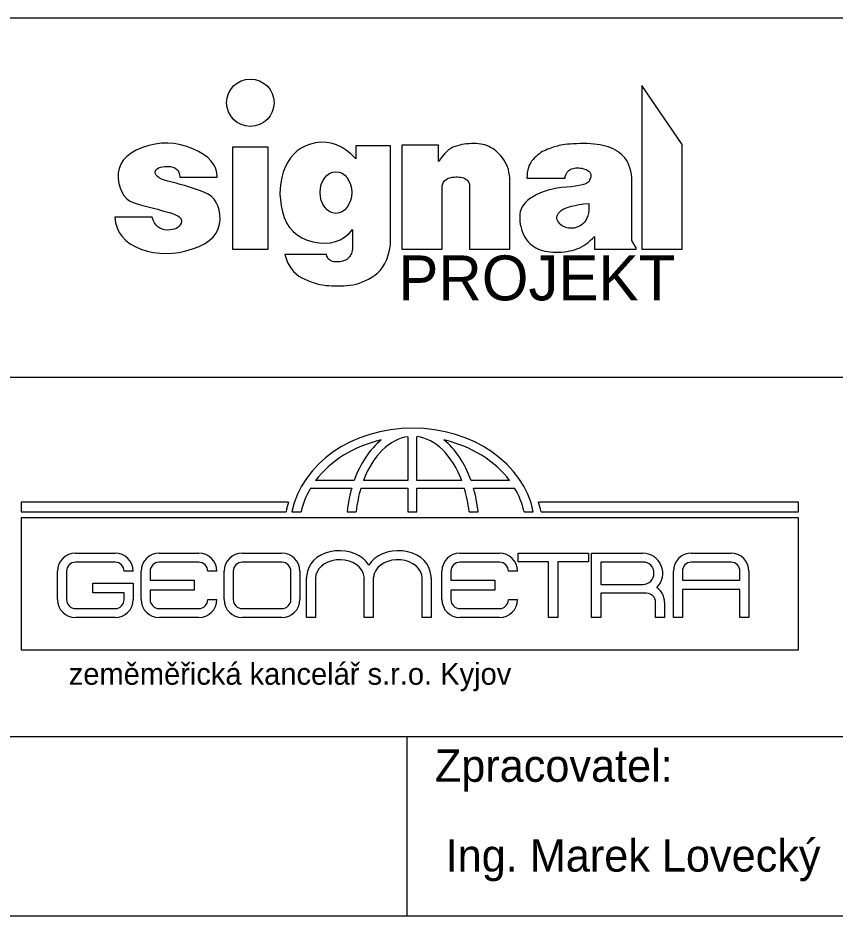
# Model space of a CAD drawing. Extents: x -553916 to -552953, y -1067469 to -1066637.
# Drawn here: x -553034.4 to -552988.9, y -1067308.3 to -1067258.3 of the extents above; entities that cross this region are included whole.
import ezdxf

# ---------------------------------------------------------------- set-up
doc = ezdxf.new("R2010")
doc.units = 0
for name, color, linetype in [('ROZPISKA', 7, 'Continuous'), ('Rozpiska_pole_6', 7, 'Continuous'), ('ZZZ - Razítko', 7, 'Continuous')]:
    doc.layers.add(name, color=color, linetype=linetype)

msp = doc.modelspace()

# ---------------------------------------------------------------- linework, layer by layer
at = {"layer": 'ROZPISKA'}
for points in [[(-552997.445, -1067271.147), (-552997.445, -1067265.307), (-552999.685, -1067262.027), (-552999.685, -1067271.147), (-552997.445, -1067271.147)], [(-553026.174, -1067271.382), (-553025.812, -1067271.366), (-553025.445, -1067271.318), (-553025.074, -1067271.239), (-553024.698, -1067271.128), (-553024.344, -1067270.992), (-553024.036, -1067270.836), (-553023.775, -1067270.66), (-553023.561, -1067270.464), (-553023.393, -1067270.248), (-553023.273, -1067270.012), (-553023.199, -1067269.756), (-553023.173, -1067269.481), (-553023.183, -1067269.207), (-553023.222, -1067268.958), (-553023.288, -1067268.734), (-553023.382, -1067268.535), (-553023.503, -1067268.36), (-553023.652, -1067268.21), (-553023.829, -1067268.084), (-553024.034, -1067267.984), (-553024.253, -1067267.898), (-553024.475, -1067267.816), (-553024.699, -1067267.738), (-553024.926, -1067267.666), (-553025.155, -1067267.597), (-553025.386, -1067267.533), (-553025.619, -1067267.473), (-553025.855, -1067267.418), (-553026.077, -1067267.363), (-553026.268, -1067267.304), (-553026.428, -1067267.241), (-553026.559, -1067267.174), (-553026.659, -1067267.102), (-553026.728, -1067267.027), (-553026.767, -1067266.948), (-553026.776, -1067266.865), (-553026.759, -1067266.785), (-553026.723, -1067266.717), (-553026.667, -1067266.659), (-553026.591, -1067266.611), (-553026.495, -1067266.575), (-553026.379, -1067266.55), (-553026.244, -1067266.535), (-553026.088, -1067266.531), (-553025.933, -1067266.542), (-553025.798, -1067266.571), (-553025.683, -1067266.619), (-553025.588, -1067266.684), (-553025.513, -1067266.768), (-553025.459, -1067266.87), (-553025.424, -1067266.991), (-553025.41, -1067267.129), (-553023.331, -1067267.129), (-553023.35, -1067266.888), (-553023.412, -1067266.658), (-553023.517, -1067266.441), (-553023.665, -1067266.237), (-553023.856, -1067266.045), (-553024.09, -1067265.866), (-553024.366, -1067265.7), (-553024.686, -1067265.547), (-553025.028, -1067265.417), (-553025.373, -1067265.323), (-553025.721, -1067265.263), (-553026.071, -1067265.238), (-553026.424, -1067265.248), (-553026.779, -1067265.293), (-553027.138, -1067265.373), (-553027.498, -1067265.487), (-553027.836, -1067265.63), (-553028.126, -1067265.792), (-553028.366, -1067265.976), (-553028.559, -1067266.18), (-553028.702, -1067266.404), (-553028.797, -1067266.649), (-553028.843, -1067266.914), (-553028.841, -1067267.2), (-553028.801, -1067267.482), (-553028.735, -1067267.734), (-553028.643, -1067267.956), (-553028.524, -1067268.149), (-553028.38, -1067268.312), (-553028.209, -1067268.446), (-553028.012, -1067268.55), (-553027.788, -1067268.625), (-553027.553, -1067268.685), (-553027.322, -1067268.745), (-553027.095, -1067268.804), (-553026.871, -1067268.863), (-553026.65, -1067268.921), (-553026.434, -1067268.98), (-553026.221, -1067269.038), (-553026.011, -1067269.096), (-553025.819, -1067269.156), (-553025.657, -1067269.22), (-553025.527, -1067269.289), (-553025.427, -1067269.362), (-553025.359, -1067269.44), (-553025.321, -1067269.523), (-553025.314, -1067269.609), (-553025.338, -1067269.701), (-553025.384, -1067269.789), (-553025.445, -1067269.865), (-553025.521, -1067269.93), (-553025.611, -1067269.983), (-553025.715, -1067270.024), (-553025.833, -1067270.054), (-553025.966, -1067270.073), (-553026.113, -1067270.079), (-553026.262, -1067270.069), (-553026.398, -1067270.036), (-553026.521, -1067269.98), (-553026.632, -1067269.902), (-553026.731, -1067269.8), (-553026.818, -1067269.677), (-553026.892, -1067269.53), (-553026.953, -1067269.362), (-553029.034, -1067269.362), (-553028.99, -1067269.668), (-553028.906, -1067269.951), (-553028.783, -1067270.208), (-553028.621, -1067270.442), (-553028.418, -1067270.652), (-553028.177, -1067270.837), (-553027.895, -1067270.998), (-553027.574, -1067271.134), (-553027.231, -1067271.243), (-553026.883, -1067271.321), (-553026.531, -1067271.367), (-553026.174, -1067271.382)], [(-553020.485, -1067271.147), (-553020.485, -1067265.467), (-553022.485, -1067265.467), (-553022.485, -1067271.147), (-553020.485, -1067271.147)], [(-553016.626, -1067273.189), (-553016.457, -1067273.186), (-553016.287, -1067273.177), (-553016.115, -1067273.164), (-553015.942, -1067273.145), (-553015.768, -1067273.119), (-553015.594, -1067273.08), (-553015.42, -1067273.028), (-553015.246, -1067272.965), (-553015.073, -1067272.89), (-553014.9, -1067272.802), (-553014.728, -1067272.702), (-553014.556, -1067272.59), (-553014.391, -1067272.461), (-553014.243, -1067272.308), (-553014.11, -1067272.132), (-553013.994, -1067271.933), (-553013.893, -1067271.711), (-553013.808, -1067271.466), (-553013.739, -1067271.198), (-553013.685, -1067270.907), (-553013.685, -1067265.387), (-553015.605, -1067265.387), (-553015.605, -1067266.107), (-553015.871, -1067265.853), (-553016.142, -1067265.64), (-553016.416, -1067265.468), (-553016.695, -1067265.337), (-553016.978, -1067265.247), (-553017.266, -1067265.198), (-553017.557, -1067265.19), (-553017.853, -1067265.224), (-553018.14, -1067265.292), (-553018.406, -1067265.389), (-553018.649, -1067265.514), (-553018.871, -1067265.668), (-553019.071, -1067265.85), (-553019.249, -1067266.061), (-553019.406, -1067266.301), (-553019.541, -1067266.568), (-553019.651, -1067266.854), (-553019.736, -1067267.147), (-553019.795, -1067267.447), (-553019.828, -1067267.755), (-553019.835, -1067268.069), (-553019.816, -1067268.391), (-553019.772, -1067268.72), (-553019.701, -1067269.056), (-553019.601, -1067269.379), (-553019.468, -1067269.67), (-553019.303, -1067269.928), (-553019.105, -1067270.154), (-553018.874, -1067270.346), (-553018.611, -1067270.506), (-553018.314, -1067270.634), (-553017.986, -1067270.728), (-553017.649, -1067270.786), (-553017.331, -1067270.804), (-553017.03, -1067270.78), (-553016.747, -1067270.716), (-553016.482, -1067270.612), (-553016.235, -1067270.466), (-553016.005, -1067270.28), (-553015.793, -1067270.053), (-553015.793, -1067271.13), (-553015.812, -1067271.217), (-553015.835, -1067271.299), (-553015.862, -1067271.375), (-553015.895, -1067271.445), (-553015.931, -1067271.51), (-553015.972, -1067271.568), (-553016.018, -1067271.621), (-553016.067, -1067271.669), (-553016.123, -1067271.71), (-553016.186, -1067271.747), (-553016.256, -1067271.778), (-553016.333, -1067271.803), (-553016.417, -1067271.823), (-553016.508, -1067271.838), (-553016.606, -1067271.847), (-553016.711, -1067271.851), (-553016.815, -1067271.846), (-553016.908, -1067271.827), (-553016.991, -1067271.796), (-553017.064, -1067271.751), (-553017.127, -1067271.692), (-553017.18, -1067271.621), (-553017.222, -1067271.536), (-553017.254, -1067271.438), (-553019.562, -1067271.438), (-553019.492, -1067271.665), (-553019.409, -1067271.874), (-553019.312, -1067272.064), (-553019.201, -1067272.236), (-553019.077, -1067272.388), (-553018.938, -1067272.522), (-553018.786, -1067272.637), (-553018.62, -1067272.734), (-553018.448, -1067272.817), (-553018.277, -1067272.891), (-553018.108, -1067272.956), (-553017.94, -1067273.013), (-553017.774, -1067273.062), (-553017.609, -1067273.102), (-553017.446, -1067273.133), (-553017.284, -1067273.155), (-553017.122, -1067273.171), (-553016.958, -1067273.182), (-553016.793, -1067273.188), (-553016.626, -1067273.189)], [(-553007.045, -1067271.147), (-553007.045, -1067267.347), (-553007.048, -1067267.177), (-553007.062, -1067267.014), (-553007.087, -1067266.857), (-553007.123, -1067266.707), (-553007.169, -1067266.564), (-553007.226, -1067266.427), (-553007.294, -1067266.297), (-553007.372, -1067266.173), (-553007.457, -1067266.057), (-553007.544, -1067265.949), (-553007.633, -1067265.849), (-553007.724, -1067265.757), (-553007.817, -1067265.674), (-553007.912, -1067265.598), (-553008.009, -1067265.531), (-553008.108, -1067265.473), (-553008.211, -1067265.421), (-553008.317, -1067265.377), (-553008.428, -1067265.34), (-553008.543, -1067265.309), (-553008.662, -1067265.286), (-553008.786, -1067265.269), (-553008.914, -1067265.259), (-553009.046, -1067265.257), (-553009.18, -1067265.26), (-553009.312, -1067265.268), (-553009.444, -1067265.281), (-553009.574, -1067265.299), (-553009.703, -1067265.322), (-553009.831, -1067265.35), (-553009.957, -1067265.382), (-553010.083, -1067265.42), (-553010.206, -1067265.468), (-553010.328, -1067265.533), (-553010.447, -1067265.614), (-553010.563, -1067265.712), (-553010.677, -1067265.826), (-553010.789, -1067265.957), (-553010.898, -1067266.104), (-553011.005, -1067266.267), (-553011.005, -1067265.347), (-553013.045, -1067265.347), (-553013.045, -1067271.147), (-553010.805, -1067271.147), (-553010.805, -1067267.587), (-553010.771, -1067267.496), (-553010.726, -1067267.415), (-553010.672, -1067267.344), (-553010.608, -1067267.283), (-553010.534, -1067267.232), (-553010.45, -1067267.191), (-553010.356, -1067267.16), (-553010.252, -1067267.139), (-553010.146, -1067267.126), (-553010.045, -1067267.119), (-553009.95, -1067267.118), (-553009.859, -1067267.124), (-553009.774, -1067267.135), (-553009.695, -1067267.153), (-553009.62, -1067267.176), (-553009.551, -1067267.206), (-553009.489, -1067267.241), (-553009.435, -1067267.279), (-553009.389, -1067267.321), (-553009.352, -1067267.367), (-553009.323, -1067267.417), (-553009.302, -1067267.47), (-553009.289, -1067267.527), (-553009.285, -1067267.587), (-553009.285, -1067271.147), (-553007.045, -1067271.147)], [(-553004.482, -1067271.311), (-553004.321, -1067271.308), (-553004.163, -1067271.3), (-553004.01, -1067271.285), (-553003.861, -1067271.265), (-553003.716, -1067271.24), (-553003.576, -1067271.208), (-553003.44, -1067271.171), (-553003.308, -1067271.128), (-553003.18, -1067271.076), (-553003.053, -1067271.015), (-553002.927, -1067270.943), (-553002.804, -1067270.861), (-553002.682, -1067270.768), (-553002.561, -1067270.665), (-553002.442, -1067270.551), (-553002.325, -1067270.427), (-553002.325, -1067271.147), (-553000.005, -1067271.147), (-553000.005, -1067271.067), (-553000.245, -1067270.667), (-553000.245, -1067267.187), (-553000.272, -1067266.983), (-553000.307, -1067266.792), (-553000.353, -1067266.617), (-553000.408, -1067266.456), (-553000.472, -1067266.309), (-553000.546, -1067266.177), (-553000.63, -1067266.059), (-553000.723, -1067265.955), (-553000.824, -1067265.863), (-553000.931, -1067265.777), (-553001.045, -1067265.698), (-553001.165, -1067265.626), (-553001.291, -1067265.561), (-553001.423, -1067265.503), (-553001.562, -1067265.452), (-553001.707, -1067265.408), (-553001.859, -1067265.37), (-553002.018, -1067265.338), (-553002.184, -1067265.311), (-553002.358, -1067265.29), (-553002.538, -1067265.275), (-553002.726, -1067265.266), (-553002.922, -1067265.262), (-553003.124, -1067265.265), (-553003.323, -1067265.271), (-553003.507, -1067265.279), (-553003.676, -1067265.289), (-553003.83, -1067265.302), (-553003.97, -1067265.317), (-553004.095, -1067265.334), (-553004.206, -1067265.354), (-553004.301, -1067265.375), (-553004.39, -1067265.399), (-553004.479, -1067265.425), (-553004.569, -1067265.452), (-553004.66, -1067265.482), (-553004.751, -1067265.513), (-553004.844, -1067265.547), (-553004.936, -1067265.582), (-553005.03, -1067265.62), (-553005.123, -1067265.661), (-553005.215, -1067265.71), (-553005.306, -1067265.765), (-553005.397, -1067265.827), (-553005.486, -1067265.896), (-553005.574, -1067265.972), (-553005.661, -1067266.055), (-553005.747, -1067266.144), (-553005.827, -1067266.242), (-553005.897, -1067266.349), (-553005.955, -1067266.465), (-553006.003, -1067266.591), (-553006.04, -1067266.726), (-553006.066, -1067266.87), (-553006.081, -1067267.024), (-553006.085, -1067267.187), (-553003.965, -1067267.187), (-553003.95, -1067267.091), (-553003.926, -1067267.004), (-553003.893, -1067266.926), (-553003.851, -1067266.857), (-553003.801, -1067266.797), (-553003.743, -1067266.747), (-553003.675, -1067266.705), (-553003.599, -1067266.673), (-553003.519, -1067266.649), (-553003.438, -1067266.631), (-553003.356, -1067266.619), (-553003.274, -1067266.615), (-553003.192, -1067266.616), (-553003.108, -1067266.625), (-553003.025, -1067266.639), (-553002.94, -1067266.661), (-553002.86, -1067266.686), (-553002.789, -1067266.714), (-553002.726, -1067266.744), (-553002.673, -1067266.776), (-553002.627, -1067266.81), (-553002.591, -1067266.846), (-553002.563, -1067266.885), (-553002.545, -1067266.925), (-553002.533, -1067266.968), (-553002.528, -1067267.014), (-553002.529, -1067267.063), (-553002.537, -1067267.114), (-553002.55, -1067267.168), (-553002.57, -1067267.225), (-553002.597, -1067267.285), (-553002.629, -1067267.348), (-553002.68, -1067267.409), (-553002.761, -1067267.465), (-553002.872, -1067267.515), (-553003.014, -1067267.561), (-553003.186, -1067267.601), (-553003.388, -1067267.636), (-553003.621, -1067267.665), (-553003.884, -1067267.689), (-553004.156, -1067267.716), (-553004.415, -1067267.753), (-553004.662, -1067267.801), (-553004.897, -1067267.86), (-553005.12, -1067267.929), (-553005.331, -1067268.008), (-553005.529, -1067268.098), (-553005.715, -1067268.199), (-553005.884, -1067268.307), (-553006.032, -1067268.42), (-553006.16, -1067268.537), (-553006.266, -1067268.659), (-553006.352, -1067268.785), (-553006.417, -1067268.915), (-553006.461, -1067269.051), (-553006.484, -1067269.19), (-553006.492, -1067269.332), (-553006.491, -1067269.472), (-553006.481, -1067269.611), (-553006.462, -1067269.749), (-553006.434, -1067269.885), (-553006.397, -1067270.021), (-553006.351, -1067270.155), (-553006.296, -1067270.288), (-553006.233, -1067270.417), (-553006.163, -1067270.536), (-553006.086, -1067270.646), (-553006.002, -1067270.748), (-553005.911, -1067270.84), (-553005.814, -1067270.924), (-553005.709, -1067270.999), (-553005.598, -1067271.065), (-553005.48, -1067271.123), (-553005.356, -1067271.173), (-553005.226, -1067271.215), (-553005.089, -1067271.25), (-553004.947, -1067271.277), (-553004.798, -1067271.296), (-553004.643, -1067271.307), (-553004.482, -1067271.311)], [(-553003.767, -1067269.967), (-553003.87, -1067269.946), (-553003.964, -1067269.918), (-553004.051, -1067269.882), (-553004.13, -1067269.839), (-553004.201, -1067269.787), (-553004.264, -1067269.728), (-553004.319, -1067269.661), (-553004.365, -1067269.587), (-553004.4, -1067269.509), (-553004.418, -1067269.432), (-553004.419, -1067269.356), (-553004.403, -1067269.281), (-553004.371, -1067269.207), (-553004.322, -1067269.134), (-553004.256, -1067269.061), (-553004.173, -1067268.99), (-553004.07, -1067268.922), (-553003.941, -1067268.859), (-553003.787, -1067268.801), (-553003.608, -1067268.748), (-553003.404, -1067268.701), (-553003.175, -1067268.659), (-553002.92, -1067268.623), (-553002.64, -1067268.592), (-553002.636, -1067268.79), (-553002.645, -1067268.972), (-553002.667, -1067269.138), (-553002.701, -1067269.288), (-553002.749, -1067269.421), (-553002.809, -1067269.539), (-553002.882, -1067269.64), (-553002.969, -1067269.725), (-553003.062, -1067269.797), (-553003.158, -1067269.856), (-553003.255, -1067269.904), (-553003.354, -1067269.94), (-553003.454, -1067269.964), (-553003.557, -1067269.977), (-553003.661, -1067269.978), (-553003.767, -1067269.967)]]:
    msp.add_lwpolyline(points, dxfattribs=at)
msp.add_circle((-553021.485, -1067262.987), 1.32, dxfattribs=at)
msp.add_ellipse((-553016.725, -1067267.987), major_axis=(0, 1.16), ratio=0.758621, dxfattribs=at)
at = {"layer": 'Rozpiska_pole_6'}
for p, q in [((-553143.11, -1067278.268), (-552973.11, -1067278.268)), ((-553143.11, -1067298.268), (-552973.11, -1067298.268)), ((-553012.76, -1067308.268), (-553012.76, -1067298.268))]:
    msp.add_line(p, q, dxfattribs=at)
msp.add_lwpolyline([(-553143.11, -1067258.268), (-552973.11, -1067258.268), (-552973.11, -1067308.268), (-553143.11, -1067308.268)], close=True, dxfattribs=at)
at = {"layer": 'ZZZ - Razítko'}
for p, q in [((-553012.715, -1067281.581), (-553012.715, -1067284.027)), ((-553012.208, -1067284.027), (-553012.208, -1067281.579)), ((-553018.128, -1067284.438), (-553015.841, -1067284.438)), ((-553015.708, -1067284.027), (-553017.853, -1067284.027)), ((-553015.331, -1067284.438), (-553012.715, -1067284.438)), ((-553012.715, -1067284.027), (-553015.191, -1067284.027)), ((-553012.715, -1067284.438), (-553012.715, -1067285.758)), ((-553009.713, -1067284.027), (-553012.208, -1067284.027)), ((-553012.208, -1067285.758), (-553012.208, -1067284.438)), ((-553012.208, -1067284.438), (-553009.574, -1067284.438)), ((-553007.051, -1067284.027), (-553009.196, -1067284.027)), ((-553009.064, -1067284.438), (-553006.776, -1067284.438)), ((-553019.359, -1067285.227), (-553034.239, -1067285.227)), ((-553034.239, -1067285.227), (-553034.239, -1067285.758)), ((-552990.961, -1067285.227), (-553005.439, -1067285.227)), ((-552990.961, -1067285.758), (-552990.961, -1067285.227)), ((-553034.239, -1067285.758), (-553019.497, -1067285.758)), ((-553019.171, -1067285.758), (-553018.654, -1067285.758)), ((-553016.098, -1067285.758), (-553015.598, -1067285.758)), ((-553012.715, -1067285.758), (-553012.208, -1067285.758)), ((-553009.307, -1067285.758), (-553008.806, -1067285.758)), ((-553006.25, -1067285.758), (-553005.733, -1067285.758)), ((-553005.301, -1067285.758), (-552990.961, -1067285.758)), ((-552990.963, -1067286.103), (-553034.246, -1067286.103)), ((-553034.246, -1067286.103), (-553034.246, -1067293.441)), ((-552990.963, -1067293.441), (-552990.963, -1067286.103)), ((-553031.221, -1067288.069), (-553029.01, -1067288.069)), ((-553026.565, -1067288.069), (-553024.354, -1067288.069)), ((-553021.941, -1067288.069), (-553019.73, -1067288.069)), ((-553009.822, -1067288.069), (-553007.612, -1067288.069)), ((-553002.485, -1067288.069), (-552999.64, -1067288.069)), ((-552996.937, -1067288.069), (-552994.726, -1067288.069)), ((-553029.01, -1067288.567), (-553031.221, -1067288.567)), ((-553024.354, -1067288.567), (-553026.565, -1067288.567)), ((-553019.73, -1067288.567), (-553021.941, -1067288.567)), ((-553007.612, -1067288.567), (-553009.822, -1067288.567)), ((-553004.879, -1067291.651), (-553004.879, -1067288.555)), ((-553004.376, -1067288.555), (-553004.376, -1067291.651)), ((-552999.64, -1067288.558), (-553001.981, -1067288.558)), ((-553001.981, -1067288.558), (-553001.981, -1067289.807)), ((-552994.726, -1067288.567), (-552996.937, -1067288.567)), ((-553032.219, -1067290.653), (-553032.219, -1067289.067)), ((-553031.72, -1067289.067), (-553031.72, -1067290.653)), ((-553028.013, -1067289.067), (-553028.511, -1067289.067)), ((-553027.562, -1067290.653), (-553027.562, -1067289.067)), ((-553027.064, -1067289.067), (-553027.064, -1067289.577)), ((-553023.356, -1067289.067), (-553023.855, -1067289.067)), ((-553022.939, -1067290.653), (-553022.939, -1067289.067)), ((-553022.44, -1067289.067), (-553022.44, -1067290.653)), ((-553019.231, -1067290.653), (-553019.231, -1067289.067)), ((-553018.732, -1067289.067), (-553018.732, -1067290.653)), ((-553018.36, -1067291.651), (-553018.36, -1067289.466)), ((-553017.859, -1067289.466), (-553017.859, -1067291.651)), ((-553015.14, -1067291.651), (-553015.14, -1067289.466)), ((-553014.639, -1067289.466), (-553014.639, -1067291.651)), ((-553011.921, -1067291.651), (-553011.921, -1067289.466)), ((-553011.42, -1067289.466), (-553011.42, -1067291.651)), ((-553010.82, -1067290.653), (-553010.82, -1067289.067)), ((-553010.321, -1067289.067), (-553010.321, -1067289.577)), ((-553006.614, -1067289.067), (-553007.112, -1067289.067)), ((-552997.935, -1067291.651), (-552997.935, -1067289.067)), ((-552997.436, -1067289.067), (-552997.436, -1067289.575)), ((-552994.227, -1067289.575), (-552994.227, -1067289.067)), ((-552993.728, -1067289.067), (-552993.728, -1067291.651)), ((-553030.246, -1067290.275), (-553030.246, -1067289.73)), ((-553030.246, -1067289.73), (-553028.013, -1067289.73)), ((-553028.013, -1067289.73), (-553028.013, -1067290.653)), ((-553027.064, -1067289.577), (-553024.621, -1067289.577)), ((-553024.621, -1067289.577), (-553024.621, -1067290.122)), ((-553010.321, -1067289.577), (-553007.878, -1067289.577)), ((-553007.878, -1067289.577), (-553007.878, -1067290.122)), ((-553001.981, -1067289.807), (-552999.64, -1067289.807)), ((-552997.436, -1067289.575), (-552994.227, -1067289.575)), ((-553028.511, -1067290.275), (-553030.246, -1067290.275)), ((-553028.511, -1067290.653), (-553028.511, -1067290.275)), ((-553024.621, -1067290.122), (-553027.064, -1067290.122)), ((-553027.064, -1067290.122), (-553027.064, -1067290.653)), ((-553007.878, -1067290.122), (-553010.321, -1067290.122)), ((-553010.321, -1067290.122), (-553010.321, -1067290.653)), ((-552999.64, -1067290.296), (-553001.981, -1067290.296)), ((-552999.426, -1067290.3), (-552999.64, -1067290.296)), ((-552994.227, -1067290.079), (-552997.436, -1067290.079)), ((-552997.436, -1067290.079), (-552997.436, -1067291.651)), ((-552994.227, -1067291.651), (-552994.227, -1067290.079)), ((-553023.855, -1067290.653), (-553023.356, -1067290.653)), ((-553007.112, -1067290.653), (-553006.614, -1067290.653)), ((-552998.927, -1067291.651), (-552998.927, -1067290.799)), ((-552998.429, -1067290.799), (-552998.429, -1067291.651)), ((-553031.221, -1067291.152), (-553029.01, -1067291.152)), ((-553026.565, -1067291.152), (-553024.354, -1067291.152)), ((-553021.941, -1067291.152), (-553019.73, -1067291.152)), ((-553009.822, -1067291.152), (-553007.612, -1067291.152)), ((-553029.01, -1067291.651), (-553031.221, -1067291.651)), ((-553024.354, -1067291.651), (-553026.565, -1067291.651)), ((-553019.73, -1067291.651), (-553021.941, -1067291.651)), ((-553017.859, -1067291.651), (-553018.36, -1067291.651)), ((-553014.639, -1067291.651), (-553015.14, -1067291.651)), ((-553011.42, -1067291.651), (-553011.921, -1067291.651)), ((-553007.612, -1067291.651), (-553009.822, -1067291.651)), ((-553004.376, -1067291.651), (-553004.879, -1067291.651)), ((-552998.429, -1067291.651), (-552998.927, -1067291.651)), ((-552997.436, -1067291.651), (-552997.935, -1067291.651)), ((-552993.728, -1067291.651), (-552994.227, -1067291.651)), ((-553034.246, -1067293.441), (-552990.963, -1067293.441))]:
    msp.add_line(p, q, dxfattribs=at)
for points in [[(-553004.879, -1067288.555), (-553006.577, -1067288.555), (-553006.577, -1067288.069), (-553002.663, -1067288.069)], [(-553002.663, -1067288.069), (-553002.663, -1067288.555), (-553004.376, -1067288.555)], [(-553001.981, -1067290.296), (-553001.981, -1067291.651), (-553002.485, -1067291.651), (-553002.485, -1067288.069)]]:
    msp.add_lwpolyline(points, dxfattribs=at)
for centre, radius, start, end in [((-553031.221, -1067289.067), 0.998, 90, 180), ((-553029.01, -1067289.067), 0.998, 360, 90), ((-553026.565, -1067289.067), 0.998, 90, 180), ((-553024.354, -1067289.067), 0.998, 360, 90), ((-553021.941, -1067289.067), 0.998, 90, 180), ((-553019.73, -1067289.067), 0.998, 360, 90), ((-553009.822, -1067289.067), 0.998, 90, 180), ((-553007.612, -1067289.067), 0.998, 360, 90), ((-552999.64, -1067289.183), 1.114, 314.4573, 90), ((-552996.937, -1067289.067), 0.998, 90, 180), ((-552994.726, -1067289.067), 0.998, 360, 90), ((-553031.221, -1067289.067), 0.499, 90, 180), ((-553029.01, -1067289.067), 0.499, 0, 90), ((-553026.565, -1067289.067), 0.499, 90, 180), ((-553024.354, -1067289.067), 0.499, 0, 90), ((-553021.941, -1067289.067), 0.499, 90, 180), ((-553019.73, -1067289.067), 0.499, 0, 90), ((-553009.822, -1067289.067), 0.499, 90, 180), ((-553007.612, -1067289.067), 0.499, 0, 90), ((-552999.64, -1067289.183), 0.625, 270, 90), ((-552996.937, -1067289.067), 0.499, 90, 180), ((-552994.726, -1067289.067), 0.499, 0, 90), ((-553016.422, -1067289.516), 1.938, 166.9658, 178.5209), ((-553016.094, -1067289.53), 0.957, 3.8649, 22.4157), ((-553013.407, -1067289.588), 1.238, 162.6139, 174.3506), ((-553013.358, -1067289.516), 1.938, 1.4791, 13.0342), ((-552999.426, -1067290.799), 0.998, 360, 55.4473), ((-552999.426, -1067290.799), 0.499, 0, 90), ((-553031.221, -1067290.653), 0.998, 180, 270), ((-553031.221, -1067290.653), 0.499, 180, 270), ((-553029.01, -1067290.653), 0.998, 270, 0), ((-553029.01, -1067290.653), 0.499, 270, 0), ((-553026.565, -1067290.653), 0.998, 180, 270), ((-553026.565, -1067290.653), 0.499, 180, 270), ((-553024.354, -1067290.653), 0.998, 270, 0), ((-553024.354, -1067290.653), 0.499, 270, 0), ((-553021.941, -1067290.653), 0.998, 180, 270), ((-553021.941, -1067290.653), 0.499, 180, 270), ((-553019.73, -1067290.653), 0.998, 270, 0), ((-553019.73, -1067290.653), 0.499, 270, 0), ((-553009.822, -1067290.653), 0.998, 180, 270), ((-553009.822, -1067290.653), 0.499, 180, 270), ((-553007.612, -1067290.653), 0.998, 270, 0), ((-553007.612, -1067290.653), 0.499, 270, 0)]:
    msp.add_arc(centre, radius, start, end, dxfattribs=at)
for centre, major_axis, ratio, start_param, end_param in [((-553012.452, -1067286.631), (-6.804, 0), 0.811768, 3.300239, 6.124539), ((-553012.452, -1067286.631), (-6.296, 0), 0.804826, 4.992897, 5.743383), ((-553012.452, -1067286.631), (0, 5.524), 0.668443, 0.491666, 1.079789), ((-553012.452, -1067286.631), (0, 5.067), 0.630136, 0.08224, 1.030995), ((-553012.452, -1067286.631), (0, 5.067), 0.630136, 5.252191, 6.206521), ((-553012.452, -1067286.631), (0, 5.524), 0.668443, 5.203397, 5.79152), ((-553012.452, -1067286.631), (-6.296, 0), 0.804826, 3.681394, 4.431881), ((-553012.452, -1067286.631), (-6.296, 0), 0.804826, 5.835664, 6.110118), ((-553012.452, -1067286.631), (0, 5.524), 0.668443, 1.16256, 1.41215), ((-553012.452, -1067286.631), (0, 5.067), 0.630136, 1.123275, 1.397729), ((-553012.452, -1067286.631), (0, 5.067), 0.630136, 4.885456, 5.159911), ((-553012.452, -1067286.631), (0, 5.524), 0.668443, 4.871035, 5.120625), ((-553012.452, -1067286.631), (-6.296, 0), 0.804826, 3.31466, 3.589114), ((-553012.778, -1067286.631), (-6.804, 0), 0.811768, 6.026233, 6.124539), ((-553012.02, -1067286.631), (-6.804, 0), 0.811768, 3.300239, 3.398545), ((-553016.531, -1067289.31), (1.805, 0), 0.766187, 0.429647, 2.97338), ((-553013.249, -1067289.31), (-1.805, 0), 0.766187, 3.309805, 5.853538), ((-553016.506, -1067289.466), (1.354, 0), 0.766187, 0.29376, 3.141593), ((-553013.274, -1067289.466), (-1.354, 0), 0.766187, 3.141593, 6.041607)]:
    msp.add_ellipse(centre, major_axis=major_axis, ratio=ratio, start_param=start_param, end_param=end_param, dxfattribs=at)

# ---------------------------------------------------------------- texts
at = {"layer": 'ROZPISKA'}
msp.add_text('PROJEKT', height=2.5, dxfattribs=at).set_placement((-553013.245, -1067273.99))
at = {"layer": 'Rozpiska_pole_6'}
for s, p in [('Zpracovatel:', (-553011.214, -1067300.795)), ('Ing. Marek Lovecký', (-553010.613, -1067305.795))]:
    msp.add_text(s, height=1.8, dxfattribs=at).set_placement(p)
at = {"layer": 'ZZZ - Razítko'}
msp.add_text('zeměměřická kancelář s.r.o. Kyjov', height=1.20984, dxfattribs=at).set_placement((-553031.594, -1067295.39))

doc.saveas('drawing.dxf')
